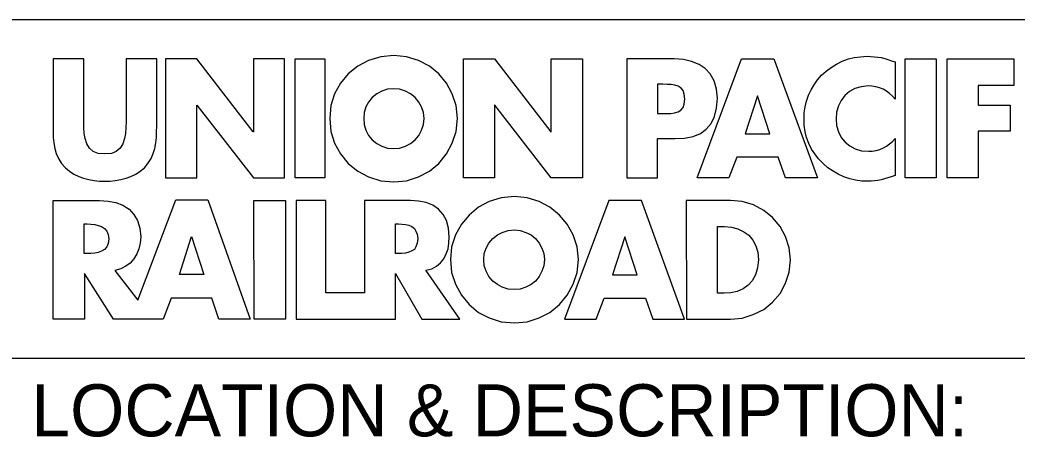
# Model space of a CAD drawing. Extents: x 0 to 1.42, y 0 to 0.92.
# Drawn here: x 1.1211 to 1.2008, y 0.0666 to 0.1 of the extents above; entities that cross this region are included whole.
import ezdxf

# ---------------------------------------------------------------- set-up
doc = ezdxf.new("R2010")
doc.units = 0
doc.layers.add('G-BORDER', color=7, linetype='Continuous')

msp = doc.modelspace()

# ---------------------------------------------------------------- linework, layer by layer
at = {"layer": 'G-BORDER'}
for p, q in [((1.3958275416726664, 0.10000271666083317), (0.9896687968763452, 0.10000271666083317)), ((1.1262090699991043, 0.09687772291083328), (1.1237519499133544, 0.09687772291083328)), ((1.1237519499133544, 0.09687772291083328), (1.1237519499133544, 0.09151910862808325)), ((1.1262090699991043, 0.09185889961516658), (1.1262090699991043, 0.09687772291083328)), ((1.1320382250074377, 0.09687772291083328), (1.1295810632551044, 0.09687772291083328)), ((1.1295810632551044, 0.09687772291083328), (1.1295810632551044, 0.09185889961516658)), ((1.1320382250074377, 0.09151910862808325), (1.1320382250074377, 0.09687772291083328)), ((1.1352272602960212, 0.09687772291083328), (1.1327440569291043, 0.09687772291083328)), ((1.1327440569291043, 0.09687772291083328), (1.1327440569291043, 0.08736290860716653)), ((1.1397494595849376, 0.09104860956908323), (1.1352272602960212, 0.09687772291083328)), ((1.1422588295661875, 0.09687772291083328), (1.1397755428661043, 0.09687772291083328)), ((1.1397755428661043, 0.09687772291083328), (1.1397755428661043, 0.09104860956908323)), ((1.1422588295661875, 0.08736290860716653), (1.1422588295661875, 0.09687772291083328)), ((1.1430952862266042, 0.09687772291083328), (1.1454740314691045, 0.09687772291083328)), ((1.1430952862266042, 0.08736290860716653), (1.1430952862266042, 0.09687772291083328)), ((1.1454740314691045, 0.09687772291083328), (1.1454740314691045, 0.08736290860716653)), ((1.1565572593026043, 0.08736290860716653), (1.1565572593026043, 0.09687772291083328)), ((1.1565572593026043, 0.09687772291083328), (1.1590404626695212, 0.09687772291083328)), ((1.1590404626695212, 0.09687772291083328), (1.1635626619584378, 0.09104860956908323)), ((1.1635887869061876, 0.09104860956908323), (1.1635887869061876, 0.09687772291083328)), ((1.1635887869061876, 0.09687772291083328), (1.1660720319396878, 0.09687772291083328)), ((1.1660720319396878, 0.09687772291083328), (1.1660720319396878, 0.08736290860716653)), ((1.173417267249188, 0.09687772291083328), (1.1696269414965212, 0.09687772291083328)), ((1.1696269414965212, 0.09687772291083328), (1.1696269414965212, 0.08736290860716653)), ((1.175247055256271, 0.08736290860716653), (1.1788020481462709, 0.09687772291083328)), ((1.1788020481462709, 0.09687772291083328), (1.1813898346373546, 0.09687772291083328)), ((1.1813898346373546, 0.09687772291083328), (1.1848664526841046, 0.08736290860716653)), ((1.1910876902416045, 0.09664247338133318), (1.1910876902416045, 0.09366260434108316)), ((1.191898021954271, 0.08736290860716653), (1.191898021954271, 0.09687772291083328)), ((1.191898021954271, 0.09687772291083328), (1.1943813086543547, 0.09687772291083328)), ((1.1943813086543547, 0.09687772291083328), (1.1943813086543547, 0.08736290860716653)), ((1.1952438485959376, 0.08736290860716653), (1.1952438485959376, 0.09687772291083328)), ((1.1952438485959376, 0.09687772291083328), (1.2005762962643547, 0.09687772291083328)), ((1.2005762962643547, 0.09687772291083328), (1.2005762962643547, 0.09476047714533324)), ((1.1725023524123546, 0.09486497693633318), (1.1720841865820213, 0.09486497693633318)), ((1.1720841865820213, 0.09486497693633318), (1.1720841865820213, 0.09251235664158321)), ((1.2005762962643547, 0.09476047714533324), (1.1977271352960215, 0.09476047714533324)), ((1.1977271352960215, 0.09476047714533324), (1.1977271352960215, 0.09319202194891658)), ((1.180082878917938, 0.09392393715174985), (1.1790895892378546, 0.09089173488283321)), ((1.181076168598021, 0.09089173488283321), (1.180082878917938, 0.09392393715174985)), ((1.1352272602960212, 0.08736290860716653), (1.1352272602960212, 0.09319202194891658)), ((1.1352272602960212, 0.09319202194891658), (1.1352534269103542, 0.09319202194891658)), ((1.1352534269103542, 0.09319202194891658), (1.1397755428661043, 0.08736290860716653)), ((1.1590665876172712, 0.09319202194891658), (1.1590404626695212, 0.09319202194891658)), ((1.1590404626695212, 0.09319202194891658), (1.1590404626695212, 0.08736290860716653)), ((1.1635887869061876, 0.08736290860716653), (1.1590665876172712, 0.09319202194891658)), ((1.1720841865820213, 0.09251235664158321), (1.1725023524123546, 0.09251235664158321)), ((1.1977271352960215, 0.09319202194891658), (1.200288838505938, 0.09319202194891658)), ((1.200288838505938, 0.09319202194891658), (1.200288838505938, 0.0911008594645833)), ((1.1397755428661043, 0.09104860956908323), (1.1397494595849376, 0.09104860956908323)), ((1.1635626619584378, 0.09104860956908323), (1.1635887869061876, 0.09104860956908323)), ((1.200288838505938, 0.0911008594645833), (1.1977271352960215, 0.0911008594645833)), ((1.1977271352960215, 0.0911008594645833), (1.1977271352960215, 0.08736290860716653)), ((1.1720841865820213, 0.09049965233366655), (1.1734957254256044, 0.09049965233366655)), ((1.1720841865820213, 0.08736290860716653), (1.1720841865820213, 0.09049965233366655)), ((1.1790895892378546, 0.09089173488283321), (1.181076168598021, 0.09089173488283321)), ((1.1910876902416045, 0.09049965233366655), (1.1910876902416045, 0.08754586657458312)), ((1.1784360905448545, 0.08900973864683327), (1.177782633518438, 0.08736290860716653)), ((1.1817297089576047, 0.08900973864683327), (1.1784360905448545, 0.08900973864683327)), ((1.182330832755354, 0.08736290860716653), (1.1817297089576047, 0.08900973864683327)), ((1.1327440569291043, 0.08736290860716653), (1.1352272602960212, 0.08736290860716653)), ((1.1397755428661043, 0.08736290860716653), (1.1422588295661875, 0.08736290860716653)), ((1.1454740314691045, 0.08736290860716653), (1.1430952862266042, 0.08736290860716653)), ((1.1590404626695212, 0.08736290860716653), (1.1565572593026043, 0.08736290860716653)), ((1.1660720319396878, 0.08736290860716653), (1.1635887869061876, 0.08736290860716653)), ((1.1696269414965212, 0.08736290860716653), (1.1720841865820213, 0.08736290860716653)), ((1.177782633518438, 0.08736290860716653), (1.175247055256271, 0.08736290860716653)), ((1.1848664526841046, 0.08736290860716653), (1.182330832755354, 0.08736290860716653)), ((1.1943813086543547, 0.08736290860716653), (1.191898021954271, 0.08736290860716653)), ((1.1977271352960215, 0.08736290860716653), (1.1952438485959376, 0.08736290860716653)), ((1.1237519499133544, 0.08555924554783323), (1.1274638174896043, 0.08555924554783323)), ((1.1237519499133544, 0.07604443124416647), (1.1237519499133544, 0.08555924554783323)), ((1.1305221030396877, 0.07756059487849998), (1.1335543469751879, 0.08561149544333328)), ((1.1335543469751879, 0.08561149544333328), (1.1361160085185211, 0.08561149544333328)), ((1.1361160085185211, 0.08561149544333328), (1.1395142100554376, 0.07604443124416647)), ((1.139827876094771, 0.07604443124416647), (1.1398017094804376, 0.08555924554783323)), ((1.1398017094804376, 0.08555924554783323), (1.142337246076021, 0.08555924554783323)), ((1.142337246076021, 0.08555924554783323), (1.142337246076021, 0.07604443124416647)), ((1.143173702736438, 0.08555924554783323), (1.143173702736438, 0.07604443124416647)), ((1.1455524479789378, 0.08555924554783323), (1.143173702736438, 0.08555924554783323)), ((1.1455524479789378, 0.07816180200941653), (1.1455524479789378, 0.08555924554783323)), ((1.152322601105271, 0.08555924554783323), (1.1486368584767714, 0.08555924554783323)), ((1.1486368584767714, 0.08555924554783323), (1.1486368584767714, 0.07816180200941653)), ((1.1681893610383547, 0.08555924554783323), (1.1646343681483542, 0.07604443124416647)), ((1.170803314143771, 0.08555924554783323), (1.1681893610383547, 0.08555924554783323)), ((1.1742537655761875, 0.07604443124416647), (1.170803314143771, 0.08555924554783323)), ((1.1779133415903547, 0.08555924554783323), (1.1743843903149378, 0.08555924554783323)), ((1.1743843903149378, 0.08555924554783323), (1.174410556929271, 0.07604443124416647)), ((1.1262352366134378, 0.08129850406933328), (1.1262352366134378, 0.08367724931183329)), ((1.1262352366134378, 0.08367724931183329), (1.1264704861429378, 0.08367724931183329)), ((1.1511201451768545, 0.08129850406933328), (1.1511201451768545, 0.08367724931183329)), ((1.1511201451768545, 0.08367724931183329), (1.1513554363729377, 0.08367724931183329)), ((1.1768676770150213, 0.07813563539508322), (1.1768676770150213, 0.08346816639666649)), ((1.1768676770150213, 0.08346816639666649), (1.1774427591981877, 0.08346816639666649)), ((1.133841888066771, 0.07962559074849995), (1.1348090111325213, 0.08265775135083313)), ((1.1348090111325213, 0.08265775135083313), (1.135802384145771, 0.07962559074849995)), ((1.169470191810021, 0.08263162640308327), (1.1684768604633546, 0.07959942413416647)), ((1.1704634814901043, 0.07959942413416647), (1.169470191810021, 0.08263162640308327)), ((1.1264704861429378, 0.08129850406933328), (1.1262352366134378, 0.08129850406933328)), ((1.1513554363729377, 0.08129850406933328), (1.1511201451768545, 0.08129850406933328)), ((1.128692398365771, 0.0799392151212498), (1.1305221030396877, 0.07756059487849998)), ((1.1562696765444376, 0.07604443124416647), (1.1535511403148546, 0.07996538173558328)), ((1.128587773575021, 0.07604443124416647), (1.1262613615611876, 0.07970396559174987)), ((1.1262613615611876, 0.07970396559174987), (1.1262613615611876, 0.07604443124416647)), ((1.135802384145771, 0.07962559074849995), (1.133841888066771, 0.07962559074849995)), ((1.1511201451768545, 0.07604443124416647), (1.1511201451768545, 0.07970396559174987)), ((1.1511201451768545, 0.07970396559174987), (1.1532374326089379, 0.07604443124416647)), ((1.1684768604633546, 0.07959942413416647), (1.1704634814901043, 0.07959942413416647)), ((1.1486368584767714, 0.07816180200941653), (1.1455524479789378, 0.07816180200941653)), ((1.1331883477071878, 0.07771742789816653), (1.1325610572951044, 0.07604443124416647)), ((1.1364297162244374, 0.07771742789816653), (1.1331883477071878, 0.07771742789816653)), ((1.137004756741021, 0.07604443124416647), (1.1364297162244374, 0.07771742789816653)), ((1.1671699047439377, 0.07604443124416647), (1.167823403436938, 0.07771742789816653)), ((1.167823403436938, 0.07771742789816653), (1.1711169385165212, 0.07771742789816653)), ((1.1711169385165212, 0.07771742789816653), (1.171718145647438, 0.07604443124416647)), ((1.1774166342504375, 0.07813563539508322), (1.1768676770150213, 0.07813563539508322)), ((1.1262613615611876, 0.07604443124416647), (1.1237519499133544, 0.07604443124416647)), ((1.1325610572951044, 0.07604443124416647), (1.128587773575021, 0.07604443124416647)), ((1.1395142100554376, 0.07604443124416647), (1.137004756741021, 0.07604443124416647)), ((1.142337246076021, 0.07604443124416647), (1.139827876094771, 0.07604443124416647)), ((1.143173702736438, 0.07604443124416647), (1.1511201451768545, 0.07604443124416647)), ((1.1532374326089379, 0.07604443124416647), (1.1562696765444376, 0.07604443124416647)), ((1.1646343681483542, 0.07604443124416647), (1.1671699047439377, 0.07604443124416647)), ((1.171718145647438, 0.07604443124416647), (1.1742537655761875, 0.07604443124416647)), ((1.174410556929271, 0.07604443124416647), (1.1779133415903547, 0.07604443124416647)), ((1.1199252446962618, 0.07291943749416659), (1.3958255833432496, 0.07291943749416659))]:
    msp.add_line(p, q, dxfattribs=at)
for points in [[(1.1509895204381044, 0.09716522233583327), (1.1499438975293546, 0.09706072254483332), (1.1489767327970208, 0.09674705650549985), (1.148114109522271, 0.09630268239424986), (1.1473560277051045, 0.095675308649), (1.1467286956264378, 0.09494343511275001), (1.1462581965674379, 0.09408081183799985), (1.1459445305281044, 0.09313973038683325), (1.1458660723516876, 0.092120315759)], [(1.1560866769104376, 0.092120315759), (1.1559821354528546, 0.09313973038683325), (1.155668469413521, 0.09408081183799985), (1.155197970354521, 0.09494343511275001), (1.1545967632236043, 0.095675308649), (1.1538386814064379, 0.09630268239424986), (1.1529760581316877, 0.09674705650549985), (1.1520089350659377, 0.09706072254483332), (1.1509895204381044, 0.09716522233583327)], [(1.1768677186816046, 0.09374097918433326), (1.1767892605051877, 0.09447285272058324), (1.1766063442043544, 0.09512635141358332), (1.1762926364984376, 0.095675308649), (1.1759005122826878, 0.09611968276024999), (1.1754038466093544, 0.09643334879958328), (1.1748027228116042, 0.09666859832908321), (1.174149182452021, 0.09682543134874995), (1.173417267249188, 0.09687772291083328)], [(1.185206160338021, 0.09557072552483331), (1.1855722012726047, 0.09591055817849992), (1.1859643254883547, 0.09619809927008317), (1.1864086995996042, 0.09645947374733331), (1.1868529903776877, 0.09669472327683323), (1.1873496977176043, 0.09687772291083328), (1.1878201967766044, 0.09698230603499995), (1.1883168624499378, 0.09706072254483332), (1.1888396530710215, 0.09711301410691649)], [(1.1888396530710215, 0.09711301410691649), (1.1891271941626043, 0.09708684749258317), (1.1894146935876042, 0.09706072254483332), (1.1897022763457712, 0.0970345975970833), (1.189963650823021, 0.09698230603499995), (1.1902511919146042, 0.09690384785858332), (1.1905125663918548, 0.09682543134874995), (1.1908001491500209, 0.09672088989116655), (1.1910876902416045, 0.09664247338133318)], [(1.1838208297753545, 0.09209423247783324), (1.1838208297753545, 0.09256464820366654), (1.1838992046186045, 0.09303523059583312), (1.1840038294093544, 0.09350572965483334), (1.1841607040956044, 0.09397622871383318), (1.1843697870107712, 0.09439447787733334), (1.1846050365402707, 0.09481268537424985), (1.1848664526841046, 0.09520472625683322), (1.185206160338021, 0.09557072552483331)], [(1.1509895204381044, 0.09449897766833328), (1.1504927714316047, 0.09444676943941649), (1.1500484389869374, 0.09428989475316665), (1.149630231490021, 0.09408081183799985), (1.149264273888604, 0.0937932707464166), (1.1489767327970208, 0.09342735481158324), (1.1487675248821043, 0.09303523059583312), (1.1486107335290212, 0.09259081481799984), (1.148584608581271, 0.092120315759)], [(1.1534204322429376, 0.092120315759), (1.1533680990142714, 0.09259081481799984), (1.1532113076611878, 0.09303523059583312), (1.1530022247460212, 0.09342735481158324), (1.1526885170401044, 0.0937932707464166), (1.1523226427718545, 0.09408081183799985), (1.1519305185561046, 0.09428989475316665), (1.1514599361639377, 0.09444676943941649), (1.1509895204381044, 0.09449897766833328)], [(1.1742798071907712, 0.09366260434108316), (1.1742275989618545, 0.09405464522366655), (1.1741230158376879, 0.09434218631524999), (1.1739661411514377, 0.09455131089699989), (1.1737309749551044, 0.0947081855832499), (1.1734696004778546, 0.0947865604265), (1.1731820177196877, 0.09483885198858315), (1.1728422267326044, 0.09483885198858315), (1.1725023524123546, 0.09486497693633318)], [(1.1889180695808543, 0.09473431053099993), (1.188369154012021, 0.09465585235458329), (1.187872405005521, 0.09452514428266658), (1.1874281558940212, 0.09426376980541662), (1.1870621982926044, 0.09395010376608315), (1.1867746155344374, 0.09355802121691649), (1.1865654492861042, 0.09311364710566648), (1.1864086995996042, 0.09261698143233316), (1.1863825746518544, 0.09209423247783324)], [(1.1910876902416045, 0.09366260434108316), (1.190878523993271, 0.09389777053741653), (1.1906432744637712, 0.09410693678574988), (1.1904080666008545, 0.09428989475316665), (1.1901204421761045, 0.09444676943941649), (1.1898329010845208, 0.09457743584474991), (1.1895454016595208, 0.09465585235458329), (1.1892317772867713, 0.0947081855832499), (1.1889180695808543, 0.09473431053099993)], [(1.1725023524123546, 0.09251235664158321), (1.1728160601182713, 0.09251235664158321), (1.1731558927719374, 0.09251235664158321), (1.1734434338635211, 0.09256464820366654), (1.1737309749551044, 0.09264310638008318), (1.1739400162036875, 0.09277385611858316), (1.1741230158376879, 0.09298293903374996), (1.1742275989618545, 0.09327048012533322), (1.1742798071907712, 0.09366260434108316)], [(1.1734957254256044, 0.09049965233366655), (1.1742537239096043, 0.09052577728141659), (1.1749333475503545, 0.0906826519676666), (1.1755084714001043, 0.09091781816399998), (1.1759789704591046, 0.09125769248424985), (1.1763710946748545, 0.09170210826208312), (1.1766323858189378, 0.09227719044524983), (1.1767892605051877, 0.09293064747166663), (1.1768677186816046, 0.09374097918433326)], [(1.1278819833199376, 0.08927111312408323), (1.127359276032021, 0.08932340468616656), (1.1269409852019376, 0.08948023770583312), (1.1266534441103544, 0.08974161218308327), (1.1264443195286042, 0.09008144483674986), (1.1263136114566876, 0.09049965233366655), (1.1262351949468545, 0.09091781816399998), (1.1262090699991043, 0.09138840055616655), (1.1262090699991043, 0.09185889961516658)], [(1.1295810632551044, 0.09185889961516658), (1.1295549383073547, 0.09138840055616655), (1.1295288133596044, 0.09091781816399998), (1.1294504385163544, 0.09049965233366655), (1.1293196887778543, 0.09008144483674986), (1.1291105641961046, 0.08974161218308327), (1.1287969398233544, 0.08948023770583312), (1.1284048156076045, 0.08932340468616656), (1.1278819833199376, 0.08927111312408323)], [(1.1458660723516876, 0.092120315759), (1.1459445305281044, 0.09107473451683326), (1.1462581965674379, 0.0901337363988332), (1.1467286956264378, 0.08927111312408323), (1.1473560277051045, 0.0885129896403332), (1.148114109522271, 0.0878856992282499), (1.1489767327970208, 0.08744136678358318), (1.1499438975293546, 0.0871276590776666), (1.1509895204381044, 0.08704924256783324)], [(1.148584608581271, 0.092120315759), (1.1486107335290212, 0.09162365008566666), (1.1487675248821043, 0.0911792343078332), (1.1489767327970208, 0.09076111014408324), (1.149264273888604, 0.09039511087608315), (1.149630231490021, 0.09010761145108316), (1.1500484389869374, 0.08989840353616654), (1.1504927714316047, 0.08974161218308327), (1.1509895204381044, 0.08971548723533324)], [(1.1509895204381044, 0.08704924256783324), (1.1520089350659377, 0.0871276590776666), (1.1529760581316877, 0.08744136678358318), (1.1538386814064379, 0.0878856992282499), (1.1545967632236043, 0.0885129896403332), (1.155197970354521, 0.08927111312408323), (1.155668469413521, 0.0901337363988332), (1.1559821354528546, 0.09107473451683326), (1.1560866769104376, 0.092120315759)], [(1.1509895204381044, 0.08971548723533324), (1.1514599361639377, 0.08974161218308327), (1.1519305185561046, 0.08989840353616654), (1.1523226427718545, 0.09010761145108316), (1.1526885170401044, 0.09039511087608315), (1.1530022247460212, 0.09076111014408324), (1.1532113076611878, 0.0911792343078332), (1.1533680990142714, 0.09162365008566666), (1.1534204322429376, 0.092120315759)], [(1.1853369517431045, 0.0885129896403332), (1.1849709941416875, 0.08887898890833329), (1.1846573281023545, 0.08927111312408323), (1.1843959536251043, 0.08966315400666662), (1.1841867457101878, 0.09010761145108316), (1.1840038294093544, 0.0905781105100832), (1.1838992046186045, 0.09104860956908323), (1.1838208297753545, 0.09157135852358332), (1.1838208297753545, 0.09209423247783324)], [(1.1863825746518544, 0.09209423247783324), (1.1864086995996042, 0.09154519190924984), (1.1865654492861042, 0.09104860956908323), (1.1867746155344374, 0.09060423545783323), (1.1870883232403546, 0.09021206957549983), (1.1874543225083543, 0.08992457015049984), (1.1878985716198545, 0.08968932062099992), (1.1883953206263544, 0.08953244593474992), (1.1889703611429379, 0.08950636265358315)], [(1.1237519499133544, 0.09151910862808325), (1.1237519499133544, 0.09104860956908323), (1.1237519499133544, 0.09060423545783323), (1.1238042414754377, 0.09015981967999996), (1.1238826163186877, 0.08971548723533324), (1.1239871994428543, 0.08929723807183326), (1.1241702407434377, 0.08890511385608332), (1.1244054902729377, 0.0885129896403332), (1.1247452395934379, 0.08817328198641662)], [(1.1310449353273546, 0.08817328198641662), (1.1313324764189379, 0.0885129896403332), (1.1315938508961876, 0.08890511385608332), (1.1317506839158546, 0.08929723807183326), (1.1318813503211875, 0.08971548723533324), (1.1319598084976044, 0.09015981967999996), (1.1320120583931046, 0.09060423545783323), (1.1320120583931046, 0.09104860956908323), (1.1320382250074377, 0.09151910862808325)], [(1.1889703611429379, 0.08950636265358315), (1.189257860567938, 0.08950636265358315), (1.189571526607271, 0.08955861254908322), (1.1898590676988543, 0.08963702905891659), (1.1901466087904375, 0.08976773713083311), (1.1904080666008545, 0.08989840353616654), (1.1906432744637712, 0.09008144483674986), (1.190878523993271, 0.09026440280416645), (1.1910876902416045, 0.09049965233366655)], [(1.1247452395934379, 0.08817328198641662), (1.1250589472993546, 0.0878856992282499), (1.1253987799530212, 0.08765044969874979), (1.125790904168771, 0.08746753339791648), (1.1261829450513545, 0.08733674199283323), (1.1266011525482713, 0.08723220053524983), (1.1270194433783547, 0.0871538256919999), (1.1274638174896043, 0.0871014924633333), (1.1278819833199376, 0.0871014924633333)], [(1.1278819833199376, 0.0871014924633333), (1.128300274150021, 0.0871014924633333), (1.1287185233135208, 0.0871538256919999), (1.1291628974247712, 0.08723220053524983), (1.1295810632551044, 0.08733674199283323), (1.1299731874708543, 0.08746753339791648), (1.1303652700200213, 0.08765044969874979), (1.1307051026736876, 0.0878856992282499), (1.1310449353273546, 0.08817328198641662)], [(1.1889180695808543, 0.0871014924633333), (1.1884214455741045, 0.0871014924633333), (1.187924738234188, 0.08717995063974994), (1.1874543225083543, 0.08728449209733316), (1.1869837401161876, 0.08744136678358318), (1.1865392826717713, 0.08765044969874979), (1.1861212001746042, 0.0878856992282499), (1.1857029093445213, 0.08817328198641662), (1.1853369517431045, 0.0885129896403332)], [(1.1910876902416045, 0.08754586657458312), (1.1907739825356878, 0.08744136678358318), (1.1905125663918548, 0.08736290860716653), (1.1902250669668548, 0.08728449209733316), (1.189963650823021, 0.08720603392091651), (1.1897022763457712, 0.0871538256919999), (1.1894408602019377, 0.0871276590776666), (1.1891794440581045, 0.0871014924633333), (1.1889180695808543, 0.0871014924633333)], [(1.1274638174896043, 0.08555924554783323), (1.1281434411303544, 0.08550699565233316), (1.1287708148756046, 0.08537624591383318), (1.1293196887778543, 0.08516716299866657), (1.1298163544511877, 0.08485349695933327), (1.130208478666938, 0.08443524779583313), (1.1304960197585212, 0.08393858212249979), (1.1306789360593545, 0.0833374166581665), (1.1307573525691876, 0.08263162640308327)], [(1.1554331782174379, 0.08263162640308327), (1.155354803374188, 0.0833374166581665), (1.1551979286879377, 0.08393858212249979), (1.154936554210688, 0.08443524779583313), (1.1545705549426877, 0.08485349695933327), (1.154126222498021, 0.08516716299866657), (1.1535773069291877, 0.08537624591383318), (1.1529760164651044, 0.08550699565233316), (1.152322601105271, 0.08555924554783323)], [(1.1606350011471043, 0.08587291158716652), (1.1595894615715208, 0.08576837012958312), (1.1586222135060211, 0.08545470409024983), (1.157759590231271, 0.08501037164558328), (1.1570277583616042, 0.08438299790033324), (1.1564004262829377, 0.0836510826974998), (1.1559298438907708, 0.08278850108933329), (1.155616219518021, 0.08184750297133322), (1.155537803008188, 0.08082804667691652)], [(1.165758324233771, 0.08082804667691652), (1.1656537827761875, 0.08184750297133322), (1.1653401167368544, 0.08278850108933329), (1.1648696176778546, 0.0836510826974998), (1.1642422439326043, 0.08438299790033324), (1.1634842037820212, 0.08501037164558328), (1.1626216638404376, 0.08545470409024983), (1.161654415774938, 0.08576837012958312), (1.1606350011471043, 0.08587291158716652)], [(1.1827229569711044, 0.08080188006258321), (1.1826183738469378, 0.08176904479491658), (1.182330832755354, 0.08265775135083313), (1.181886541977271, 0.08346816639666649), (1.1812852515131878, 0.08417387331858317), (1.1805795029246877, 0.08474895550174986), (1.1797691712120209, 0.08519332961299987), (1.1788543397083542, 0.08545470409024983), (1.1779133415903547, 0.08555924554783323)], [(1.1264704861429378, 0.08367724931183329), (1.1267579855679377, 0.0836510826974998), (1.1270716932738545, 0.08362495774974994), (1.127359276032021, 0.08354649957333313), (1.1276206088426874, 0.08346816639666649), (1.1278558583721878, 0.0833112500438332), (1.1280388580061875, 0.08310216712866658), (1.1281434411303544, 0.08281462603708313), (1.1281957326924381, 0.08247479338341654)], [(1.1513554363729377, 0.08367724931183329), (1.1516429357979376, 0.0836510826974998), (1.1519304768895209, 0.08362495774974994), (1.1521918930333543, 0.08357266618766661), (1.1524271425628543, 0.08346816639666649), (1.1526363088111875, 0.0833112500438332), (1.152766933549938, 0.08310216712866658), (1.1528714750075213, 0.08284075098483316), (1.1529237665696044, 0.08250091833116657)], [(1.1582040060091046, 0.08082804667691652), (1.1582301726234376, 0.08129850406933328), (1.1583869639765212, 0.08174287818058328), (1.1585960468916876, 0.08213500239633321), (1.1589097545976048, 0.08250091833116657), (1.1592757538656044, 0.08278850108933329), (1.1596678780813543, 0.0829975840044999), (1.1601382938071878, 0.08315445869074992), (1.1606350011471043, 0.08320666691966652)], [(1.1606350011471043, 0.08320666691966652), (1.1611055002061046, 0.08315445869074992), (1.1615498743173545, 0.0829975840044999), (1.1619681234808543, 0.08278850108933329), (1.162334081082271, 0.08250091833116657), (1.1626216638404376, 0.08213500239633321), (1.162830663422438, 0.08174287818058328), (1.1629875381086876, 0.08129850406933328), (1.1630398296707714, 0.08082804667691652)], [(1.1774427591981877, 0.08346816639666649), (1.1779917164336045, 0.08341583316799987), (1.1785145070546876, 0.08328512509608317), (1.1789850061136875, 0.08304987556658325), (1.1793771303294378, 0.0827623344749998), (1.179716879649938, 0.08237025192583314), (1.1799521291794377, 0.08192587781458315), (1.1801090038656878, 0.08140304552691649), (1.1801612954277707, 0.08080188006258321)], [(1.1281957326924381, 0.08247479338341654), (1.1281434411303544, 0.08210887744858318), (1.1280388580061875, 0.08184750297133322), (1.1278558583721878, 0.08163829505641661), (1.1276206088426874, 0.08148150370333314), (1.127359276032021, 0.08137692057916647), (1.1270716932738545, 0.08132458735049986), (1.1267579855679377, 0.08129850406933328), (1.1264704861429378, 0.08129850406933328)], [(1.1307573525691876, 0.08263162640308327), (1.1307051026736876, 0.08213500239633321), (1.1306005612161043, 0.08169062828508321), (1.1304436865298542, 0.08127233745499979), (1.130208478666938, 0.08088025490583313), (1.129920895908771, 0.08054042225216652), (1.129555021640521, 0.08027904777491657), (1.1291628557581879, 0.0800699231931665), (1.128692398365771, 0.0799392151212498)], [(1.1529237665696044, 0.08250091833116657), (1.1528714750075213, 0.08213500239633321), (1.152766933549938, 0.08184750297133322), (1.1526363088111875, 0.08163829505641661), (1.1524271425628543, 0.08150762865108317), (1.1521918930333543, 0.08140304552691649), (1.1519304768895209, 0.08132458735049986), (1.1516429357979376, 0.08129850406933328), (1.1513554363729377, 0.08129850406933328)], [(1.1535511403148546, 0.07996538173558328), (1.1540216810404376, 0.0800699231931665), (1.1544137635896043, 0.08027904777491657), (1.1547274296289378, 0.08056658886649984), (1.1549888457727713, 0.08088025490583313), (1.1551718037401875, 0.08127233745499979), (1.1553286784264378, 0.08169062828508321), (1.1554070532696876, 0.08213500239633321), (1.1554331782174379, 0.08263162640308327)], [(1.155537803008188, 0.08082804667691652), (1.155616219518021, 0.07978238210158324), (1.1559298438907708, 0.07884138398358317), (1.1564004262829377, 0.07797876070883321), (1.1570277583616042, 0.07722076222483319), (1.157759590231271, 0.07659338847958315), (1.1586222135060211, 0.0761490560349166), (1.1595894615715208, 0.07583534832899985), (1.1606350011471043, 0.07575689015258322)], [(1.1606350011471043, 0.0784231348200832), (1.1601382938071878, 0.07844925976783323), (1.1596678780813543, 0.07860609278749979), (1.1592757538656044, 0.07881525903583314), (1.1589097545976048, 0.07910280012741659), (1.1585960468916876, 0.07946875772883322), (1.1583869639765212, 0.07988700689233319), (1.1582301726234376, 0.08033133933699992), (1.1582040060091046, 0.08082804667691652)], [(1.1606350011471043, 0.07575689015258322), (1.161654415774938, 0.07583534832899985), (1.1626216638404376, 0.0761490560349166), (1.1634842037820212, 0.07659338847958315), (1.1642422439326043, 0.07722076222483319), (1.1648696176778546, 0.07797876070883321), (1.1653401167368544, 0.07884138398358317), (1.1656537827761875, 0.07978238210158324), (1.165758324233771, 0.08082804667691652)], [(1.1630398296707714, 0.08082804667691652), (1.1629875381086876, 0.08033133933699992), (1.162830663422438, 0.07988700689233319), (1.1626216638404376, 0.07946875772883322), (1.162334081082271, 0.07910280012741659), (1.1619681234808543, 0.07881525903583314), (1.1615498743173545, 0.07860609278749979), (1.1611055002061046, 0.07844925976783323), (1.1606350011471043, 0.0784231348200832)], [(1.1801612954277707, 0.08080188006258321), (1.180082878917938, 0.08014838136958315), (1.1799260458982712, 0.07959942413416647), (1.1796645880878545, 0.07912892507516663), (1.1793248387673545, 0.0787629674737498), (1.178932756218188, 0.07847542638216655), (1.1784622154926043, 0.0782662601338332), (1.1779394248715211, 0.07816180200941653), (1.1774166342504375, 0.07813563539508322)], [(1.1779133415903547, 0.07604443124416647), (1.1788543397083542, 0.0761228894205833), (1.1797430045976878, 0.07641038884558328), (1.1805795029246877, 0.07682867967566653), (1.1812852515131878, 0.07740372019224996), (1.181886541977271, 0.07810951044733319), (1.182330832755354, 0.07891975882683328), (1.1826183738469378, 0.07980854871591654), (1.1827229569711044, 0.08080188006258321)]]:
    msp.add_lwpolyline(points, dxfattribs=at)

# ---------------------------------------------------------------- texts
msp.add_text('LOCATION & DESCRIPTION:', height=0.0041666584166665, rotation=0.004008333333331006, dxfattribs=at).set_placement((1.1220088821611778, 0.0666694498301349))

doc.saveas('drawing.dxf')
